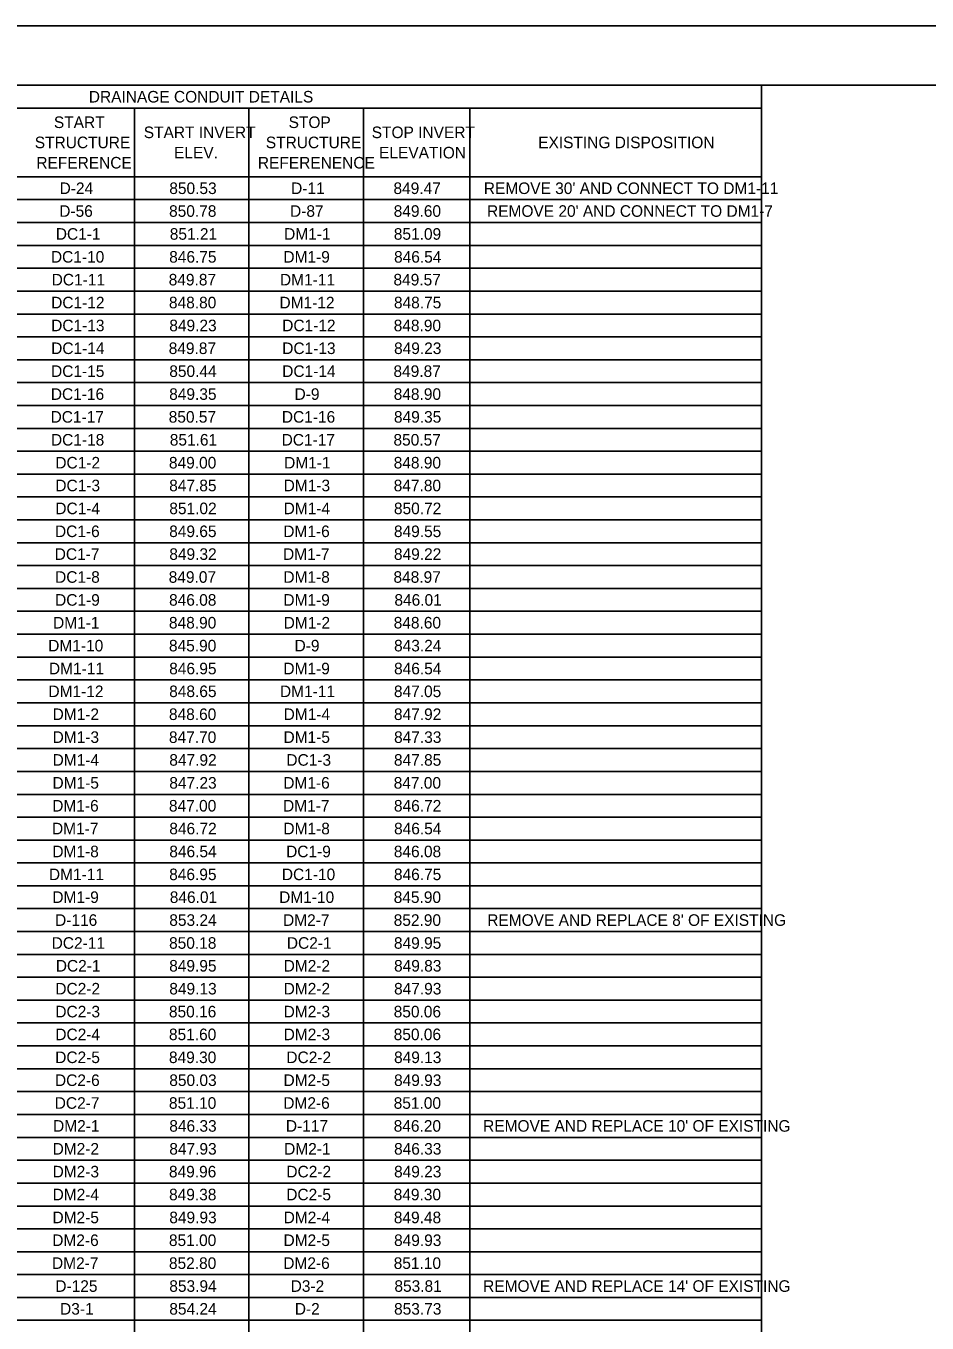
# Model space of a CAD drawing. Extents: x 0 to 34, y 0 to 22.
# Drawn here: x 4.97 to 12.56, y 11.07 to 22 of the extents above; entities that cross this region are included whole.
import ezdxf

# ---------------------------------------------------------------- set-up
doc = ezdxf.new("R2010")
doc.units = 0
for name, color, linetype in [('SH_Border', 7, 'Continuous'), ('SH_Cut_Line', 7, 'Continuous'), ('SH_Text', 7, 'Continuous')]:
    doc.layers.add(name, color=color, linetype=linetype)

msp = doc.modelspace()

# ---------------------------------------------------------------- linework, layer by layer
at = {"layer": 'SH_Border'}
msp.add_lwpolyline([(1.5, 21.5), (33.5, 21.5), (33.5, 0.5), (1.5, 0.5)], close=True, dxfattribs=at)
at = {"layer": 'SH_Cut_Line'}
msp.add_lwpolyline([(0, 0), (34, 0), (34, 22), (0, 22)], close=True, dxfattribs=at)
at = {"layer": 'SH_Text'}
for p, q in [((1.5, 21.5), (11.162, 21.5)), ((11.162, 21.5), (11.162, 3.197)), ((1.5, 21.307), (11.162, 21.307)), ((5.883, 21.307), (5.883, 3.197)), ((6.846, 21.307), (6.846, 3.197)), ((7.81, 21.307), (7.81, 3.197)), ((8.706, 21.307), (8.706, 3.197)), ((1.5, 20.729), (11.162, 20.729)), ((2.068, 20.537), (11.162, 20.537)), ((2.068, 20.344), (11.162, 20.344)), ((2.068, 20.151), (11.162, 20.151)), ((2.068, 19.959), (11.162, 19.959)), ((2.068, 19.766), (11.162, 19.766)), ((2.068, 19.573), (11.162, 19.573)), ((2.068, 19.381), (11.162, 19.381)), ((2.068, 19.188), (11.162, 19.188)), ((2.068, 18.995), (11.162, 18.995)), ((2.068, 18.803), (11.162, 18.803)), ((2.068, 18.61), (11.162, 18.61)), ((2.068, 18.417), (11.162, 18.417)), ((2.068, 18.225), (11.162, 18.225)), ((2.068, 18.032), (11.162, 18.032)), ((2.068, 17.839), (11.162, 17.839)), ((2.068, 17.647), (11.162, 17.647)), ((2.068, 17.454), (11.162, 17.454)), ((2.068, 17.261), (11.162, 17.261)), ((2.068, 17.069), (11.162, 17.069)), ((2.068, 16.876), (11.162, 16.876)), ((2.068, 16.683), (11.162, 16.683)), ((2.068, 16.491), (11.162, 16.491)), ((2.068, 16.298), (11.162, 16.298)), ((2.068, 16.105), (11.162, 16.105)), ((2.068, 15.913), (11.162, 15.913)), ((2.068, 15.72), (11.162, 15.72)), ((2.068, 15.527), (11.162, 15.527)), ((2.068, 15.335), (11.162, 15.335)), ((2.068, 15.142), (11.162, 15.142)), ((2.068, 14.949), (11.162, 14.949)), ((2.068, 14.757), (11.162, 14.757)), ((1.5, 14.564), (11.162, 14.564)), ((2.068, 14.371), (11.162, 14.371)), ((2.068, 14.179), (11.162, 14.179)), ((2.068, 13.986), (11.162, 13.986)), ((2.068, 13.793), (11.162, 13.793)), ((2.068, 13.601), (11.162, 13.601)), ((2.068, 13.408), (11.162, 13.408)), ((2.068, 13.215), (11.162, 13.215)), ((2.068, 13.023), (11.162, 13.023)), ((2.068, 12.83), (11.162, 12.83)), ((2.068, 12.637), (11.162, 12.637)), ((2.068, 12.445), (11.162, 12.445)), ((2.068, 12.252), (11.162, 12.252)), ((2.068, 12.059), (11.162, 12.059)), ((2.068, 11.867), (11.162, 11.867)), ((2.068, 11.674), (11.162, 11.674)), ((1.5, 11.481), (11.162, 11.481)), ((2.068, 11.289), (11.162, 11.289)), ((2.068, 11.096), (11.162, 11.096))]:
    msp.add_line(p, q, dxfattribs=at)

# ---------------------------------------------------------------- texts
for s, height, p in [('DRAINAGE CONDUIT DETAILS', 0.09749, (5.497, 21.355)), ('START ', 0.0975, (5.203, 21.14)), ('STOP ', 0.0975, (7.18, 21.14)), ('START INVERT ', 0.09749, (5.96, 21.055)), ('STOP INVERT ', 0.09749, (7.88, 21.055)), ('STRUCTURE ', 0.0975, (5.042, 20.97)), ('ELEV.', 0.0975, (6.215, 20.884)), ('STRUCTURE ', 0.0975, (6.988, 20.97)), ('ELEVATION', 0.0975, (7.942, 20.884)), ('EXISTING DISPOSITION', 0.09749, (9.282, 20.97)), ('REFERENCE', 0.0975, (5.055, 20.799)), ('REFERENENCE', 0.09749, (6.921, 20.799)), ('D-24', 0.0975, (5.251, 20.584)), ('850.53', 0.0975, (6.175, 20.584)), ('D-11', 0.0975, (7.201, 20.584)), ('849.47', 0.0975, (8.063, 20.584)), ("REMOVE 30' AND CONNECT TO DM1-11", 0.09749, (8.824, 20.584)), ('D-56', 0.0975, (5.248, 20.392)), ('850.78', 0.0975, (6.173, 20.392)), ('D-87', 0.0975, (7.192, 20.392)), ('849.60', 0.0975, (8.065, 20.392)), ("REMOVE 20' AND CONNECT TO DM1-7", 0.09749, (8.851, 20.392)), ('DC1-1', 0.0975, (5.219, 20.199)), ('851.21', 0.0975, (6.179, 20.199)), ('DM1-1', 0.0975, (7.142, 20.199)), ('851.09', 0.0975, (8.066, 20.199)), ('DC1-10', 0.0975, (5.178, 20.006)), ('846.75', 0.0975, (6.174, 20.006)), ('DM1-9', 0.0975, (7.136, 20.006)), ('846.54', 0.0975, (8.068, 20.006)), ('DC1-11', 0.0975, (5.184, 19.814)), ('849.87', 0.0975, (6.17, 19.814)), ('DM1-11', 0.0975, (7.107, 19.814)), ('849.57', 0.0975, (8.063, 19.814)), ('DC1-12', 0.0975, (5.18, 19.621)), ('848.80', 0.0975, (6.172, 19.621)), ('DM1-12', 0.0975, (7.103, 19.621)), ('848.75', 0.0975, (8.067, 19.621)), ('DC1-13', 0.0975, (5.18, 19.428)), ('849.23', 0.0975, (6.175, 19.428)), ('DC1-12', 0.0975, (7.126, 19.428)), ('848.90', 0.0975, (8.065, 19.428)), ('DC1-14', 0.0975, (5.18, 19.236)), ('849.87', 0.0975, (6.17, 19.236)), ('DC1-13', 0.0975, (7.126, 19.236)), ('849.23', 0.0975, (8.068, 19.236)), ('DC1-15', 0.0975, (5.179, 19.043)), ('850.44', 0.0975, (6.175, 19.043)), ('DC1-14', 0.0975, (7.126, 19.043)), ('849.87', 0.0975, (8.063, 19.043)), ('DC1-16', 0.0975, (5.177, 18.85)), ('849.35', 0.0975, (6.174, 18.85)), ('D-9', 0.0975, (7.23, 18.85)), ('848.90', 0.0975, (8.065, 18.85)), ('DC1-17', 0.0975, (5.175, 18.658)), ('850.57', 0.0975, (6.17, 18.658)), ('DC1-16', 0.0975, (7.123, 18.658)), ('849.35', 0.0975, (8.067, 18.658)), ('DC1-18', 0.0975, (5.178, 18.465)), ('851.61', 0.0975, (6.179, 18.465)), ('DC1-17', 0.0975, (7.121, 18.465)), ('850.57', 0.0975, (8.063, 18.465)), ('DC1-2', 0.0975, (5.215, 18.272)), ('849.00', 0.0975, (6.172, 18.272)), ('DM1-1', 0.0975, (7.142, 18.272)), ('848.90', 0.0975, (8.065, 18.272)), ('DC1-3', 0.0975, (5.215, 18.08)), ('847.85', 0.0975, (6.174, 18.08)), ('DM1-3', 0.0975, (7.138, 18.08)), ('847.80', 0.0975, (8.065, 18.08)), ('DC1-4', 0.0975, (5.215, 17.887)), ('851.02', 0.0975, (6.175, 17.887)), ('DM1-4', 0.0975, (7.138, 17.887)), ('850.72', 0.0975, (8.067, 17.887)), ('DC1-6', 0.0975, (5.212, 17.694)), ('849.65', 0.0975, (6.174, 17.694)), ('DM1-6', 0.0975, (7.135, 17.694)), ('849.55', 0.0975, (8.067, 17.694)), ('DC1-7', 0.0975, (5.21, 17.502)), ('849.32', 0.0975, (6.175, 17.502)), ('DM1-7', 0.0975, (7.133, 17.502)), ('849.22', 0.0975, (8.067, 17.502)), ('DC1-8', 0.0975, (5.213, 17.309)), ('849.07', 0.0975, (6.17, 17.309)), ('DM1-8', 0.0975, (7.136, 17.309)), ('848.97', 0.0975, (8.063, 17.309)), ('DC1-9', 0.0975, (5.213, 17.116)), ('846.08', 0.0975, (6.173, 17.116)), ('DM1-9', 0.0975, (7.136, 17.116)), ('846.01', 0.0975, (8.071, 17.116)), ('DM1-1', 0.0975, (5.196, 16.924)), ('848.90', 0.0975, (6.172, 16.924)), ('DM1-2', 0.0975, (7.138, 16.924)), ('848.60', 0.0975, (8.065, 16.924)), ('DM1-10', 0.0975, (5.155, 16.731)), ('845.90', 0.0975, (6.172, 16.731)), ('D-9', 0.0975, (7.23, 16.731)), ('843.24', 0.0975, (8.068, 16.731)), ('DM1-11', 0.0975, (5.161, 16.538)), ('846.95', 0.0975, (6.174, 16.538)), ('DM1-9', 0.0975, (7.136, 16.538)), ('846.54', 0.0975, (8.068, 16.538)), ('DM1-12', 0.0975, (5.157, 16.346)), ('848.65', 0.0975, (6.174, 16.346)), ('DM1-11', 0.0975, (7.107, 16.346)), ('847.05', 0.0975, (8.067, 16.346)), ('DM1-2', 0.0975, (5.192, 16.153)), ('848.60', 0.0975, (6.172, 16.153)), ('DM1-4', 0.0975, (7.138, 16.153)), ('847.92', 0.0975, (8.067, 16.153)), ('DM1-3', 0.0975, (5.192, 15.96)), ('847.70', 0.0975, (6.172, 15.96)), ('DM1-5', 0.0975, (7.137, 15.96)), ('847.33', 0.0975, (8.068, 15.96)), ('DM1-4', 0.0975, (5.192, 15.768)), ('847.92', 0.0975, (6.175, 15.768)), ('DC1-3', 0.0975, (7.161, 15.768)), ('847.85', 0.0975, (8.067, 15.768)), ('DM1-5', 0.0975, (5.191, 15.575)), ('847.23', 0.0975, (6.175, 15.575)), ('DM1-6', 0.0975, (7.135, 15.575)), ('847.00', 0.0975, (8.065, 15.575)), ('DM1-6', 0.0975, (5.189, 15.382)), ('847.00', 0.0975, (6.172, 15.382)), ('DM1-7', 0.0975, (7.133, 15.382)), ('846.72', 0.0975, (8.067, 15.382)), ('DM1-7', 0.0975, (5.187, 15.19)), ('846.72', 0.0975, (6.175, 15.19)), ('DM1-8', 0.0975, (7.136, 15.19)), ('846.54', 0.0975, (8.068, 15.19)), ('DM1-8', 0.0975, (5.19, 14.997)), ('846.54', 0.0975, (6.175, 14.997)), ('DC1-9', 0.0975, (7.159, 14.997)), ('846.08', 0.0975, (8.066, 14.997)), ('DM1-11', 0.0975, (5.161, 14.804)), ('846.95', 0.0975, (6.174, 14.804)), ('DC1-10', 0.0975, (7.123, 14.804)), ('846.75', 0.0975, (8.067, 14.804)), ('DM1-9', 0.0975, (5.19, 14.612)), ('846.01', 0.0975, (6.179, 14.612)), ('DM1-10', 0.0975, (7.1, 14.612)), ('845.90', 0.0975, (8.065, 14.612)), ('D-116', 0.0975, (5.213, 14.419)), ('853.24', 0.0975, (6.175, 14.419)), ('DM2-7', 0.0975, (7.133, 14.419)), ('852.90', 0.0975, (8.065, 14.419)), ("REMOVE AND REPLACE 8' OF EXISTING", 0.09749, (8.853, 14.419)), ('DC2-11', 0.0975, (5.184, 14.226)), ('850.18', 0.0975, (6.173, 14.226)), ('DC2-1', 0.0975, (7.165, 14.226)), ('849.95', 0.0975, (8.067, 14.226)), ('DC2-1', 0.0975, (5.219, 14.034)), ('849.95', 0.0975, (6.174, 14.034)), ('DM2-2', 0.0975, (7.138, 14.034)), ('849.83', 0.0975, (8.068, 14.034)), ('DC2-2', 0.0975, (5.215, 13.841)), ('849.13', 0.0975, (6.175, 13.841)), ('DM2-2', 0.0975, (7.138, 13.841)), ('847.93', 0.0975, (8.068, 13.841)), ('DC2-3', 0.0975, (5.215, 13.648)), ('850.16', 0.0975, (6.172, 13.648)), ('DM2-3', 0.0975, (7.138, 13.648)), ('850.06', 0.0975, (8.065, 13.648)), ('DC2-4', 0.0975, (5.215, 13.456)), ('851.60', 0.0975, (6.172, 13.456)), ('DM2-3', 0.0975, (7.138, 13.456)), ('850.06', 0.0975, (8.065, 13.456)), ('DC2-5', 0.0975, (5.214, 13.263)), ('849.30', 0.0975, (6.172, 13.263)), ('DC2-2', 0.0975, (7.161, 13.263)), ('849.13', 0.0975, (8.068, 13.263)), ('DC2-6', 0.0975, (5.212, 13.07)), ('850.03', 0.0975, (6.175, 13.07)), ('DM2-5', 0.0975, (7.137, 13.07)), ('849.93', 0.0975, (8.068, 13.07)), ('DC2-7', 0.0975, (5.21, 12.878)), ('851.10', 0.0975, (6.172, 12.878)), ('DM2-6', 0.0975, (7.135, 12.878)), ('851.00', 0.0975, (8.065, 12.878)), ('DM2-1', 0.0975, (5.196, 12.685)), ('846.33', 0.0975, (6.175, 12.685)), ('D-117', 0.0975, (7.157, 12.685)), ('846.20', 0.0975, (8.065, 12.685)), ("REMOVE AND REPLACE 10' OF EXISTING", 0.09749, (8.818, 12.685)), ('DM2-2', 0.0975, (5.192, 12.492)), ('847.93', 0.0975, (6.175, 12.492)), ('DM2-1', 0.0975, (7.142, 12.492)), ('846.33', 0.0975, (8.068, 12.492)), ('DM2-3', 0.0975, (5.192, 12.3)), ('849.96', 0.0975, (6.172, 12.3)), ('DC2-2', 0.0975, (7.161, 12.3)), ('849.23', 0.0975, (8.068, 12.3)), ('DM2-4', 0.0975, (5.192, 12.107)), ('849.38', 0.0975, (6.173, 12.107)), ('DC2-5', 0.0975, (7.16, 12.107)), ('849.30', 0.0975, (8.065, 12.107)), ('DM2-5', 0.0975, (5.191, 11.914)), ('849.93', 0.0975, (6.175, 11.914)), ('DM2-4', 0.0975, (7.138, 11.914)), ('849.48', 0.0975, (8.066, 11.914)), ('DM2-6', 0.0975, (5.189, 11.722)), ('851.00', 0.0975, (6.172, 11.722)), ('DM2-5', 0.0975, (7.137, 11.722)), ('849.93', 0.0975, (8.068, 11.722)), ('DM2-7', 0.0975, (5.187, 11.529)), ('852.80', 0.0975, (6.172, 11.529)), ('DM2-6', 0.0975, (7.135, 11.529)), ('851.10', 0.0975, (8.065, 11.529)), ('D-125', 0.0975, (5.215, 11.336)), ('853.94', 0.0975, (6.175, 11.336)), ('D3-2', 0.0975, (7.197, 11.336)), ('853.81', 0.0975, (8.071, 11.336)), ("REMOVE AND REPLACE 14' OF EXISTING", 0.09749, (8.818, 11.336)), ('D3-1', 0.0975, (5.255, 11.144)), ('854.24', 0.0975, (6.175, 11.144)), ('D-2', 0.0975, (7.232, 11.144)), ('853.73', 0.0975, (8.068, 11.144))]:
    msp.add_text(s, height=height, dxfattribs=at).set_placement(p)

doc.saveas('drawing.dxf')
